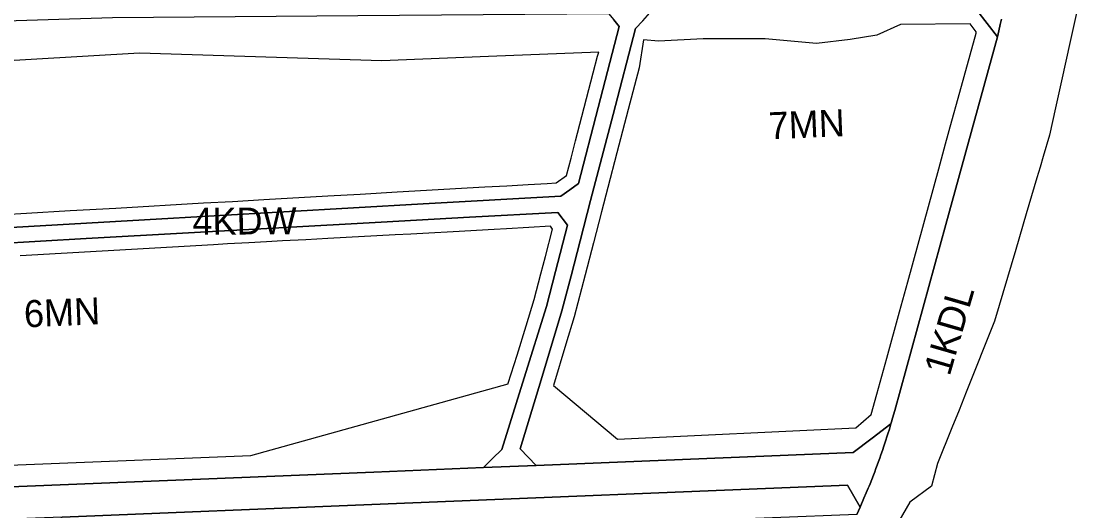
# Model space of a CAD drawing. Extents: x 7418021 to 7419743, y 5540231 to 5541685.
# Drawn here: x 7419339.9 to 7419732.3, y 5540844.3 to 5541025.9 of the extents above; entities that cross this region are included whole.
import ezdxf

# ---------------------------------------------------------------- set-up
doc = ezdxf.new("R2010")
doc.units = 0
for name, color, linetype in [('linie_rozgraniczajace', 7, 'Continuous'), ('linie_zabudowy_nieprzekraczalne', 7, 'Continuous'), ('linie_zabudowy_obowiazujace', 7, 'Continuous'), ('oznaczenia_przeznaczen', 7, 'Continuous')]:
    doc.layers.add(name, color=color, linetype=linetype)

msp = doc.modelspace()

# ---------------------------------------------------------------- linework, layer by layer
at = {"layer": 'linie_rozgraniczajace'}
for points in [[(7419573.14, 5541028.94), (7419627.51, 5541029.4), (7419694.39, 5541029.96), (7419702.04, 5541020.06), (7419682.92, 5540950.48), (7419663.99, 5540881.59), (7419663.17, 5540878.7), (7419662.77, 5540877.34), (7419662.54, 5540876.55), (7419655.53, 5540871.26), (7419648.52, 5540865.96), (7419530.9, 5540861.18), (7419527.93, 5540864.25), (7419524.97, 5540867.31), (7419532.73, 5540892.9), (7419540.49, 5540918.5), (7419543.88, 5540931.49), (7419547.26, 5540944.48), (7419551.14, 5540959.4), (7419559.45, 5540991.31), (7419567.76, 5541023.22), (7419570.45, 5541026.08)], [(7419095.29, 5541018.74), (7419234.54, 5541023), (7419373.79, 5541027.27), (7419464.79, 5541028.03), (7419557.71, 5541028.81), (7419559.74, 5541026.38), (7419561.78, 5541023.94), (7419553.94, 5540993.88), (7419546.61, 5540965.74), (7419543.38, 5540963.37), (7419540.14, 5540961), (7419488.96, 5540958.13), (7419385.59, 5540952.23), (7419282.22, 5540946.32), (7419257.39, 5540947.92), (7419232.55, 5540949.52), (7419183.71, 5540952.61), (7419134.88, 5540955.7), (7419086.04, 5540958.8), (7419083.17, 5540961.6), (7419080.29, 5540964.41), (7419084.37, 5541008.48)], [(7419355.09, 5540842.04), (7419469.94, 5540846.7), (7419646.42, 5540853.87), (7419651.11, 5540845.7), (7419649.87, 5540842.99), (7419587.34, 5540840.46), (7419524.8, 5540837.92), (7419498.8, 5540836.95), (7419498.21, 5540816.69), (7419497.63, 5540796.42), (7419468.2, 5540795.38), (7419438.78, 5540794.34), (7419439.03, 5540813.98), (7419439.29, 5540833.62), (7419394.19, 5540831.79), (7419349.1, 5540829.96), (7419349.21, 5540833.97), (7419352.15, 5540838.02)]]:
    msp.add_lwpolyline(points, close=True, dxfattribs=at)
for points in [[(7419732.26, 5541032.84), (7419729.06, 5541018.33), (7419725.85, 5541003.82), (7419723.64, 5540993.74), (7419721.43, 5540983.66), (7419719.06, 5540975.72), (7419717.88, 5540971.76), (7419716.7, 5540967.79), (7419712.77, 5540954.52), (7419708.85, 5540941.26), (7419701.01, 5540914.73), (7419690.44, 5540888.3), (7419687.8, 5540881.69), (7419685.16, 5540875.09), (7419679.88, 5540861.87), (7419677.58, 5540853.52), (7419669.56, 5540847.51), (7419663.65, 5540837.34)], [(7419703.59, 5541026.71), (7419703.12, 5541024.71), (7419702.58, 5541022.37), (7419702.04, 5541020.06), (7419694.39, 5541029.96)], [(7419282.22, 5540946.32), (7419385.59, 5540952.23), (7419488.96, 5540958.13), (7419540.14, 5540961), (7419543.38, 5540963.37), (7419546.61, 5540965.74), (7419553.94, 5540993.88), (7419561.78, 5541023.94), (7419559.74, 5541026.38)], [(7419570.45, 5541026.08), (7419567.76, 5541023.22), (7419559.45, 5540991.31), (7419551.14, 5540959.4), (7419547.26, 5540944.48), (7419543.88, 5540931.49), (7419540.49, 5540918.5), (7419532.73, 5540892.9), (7419524.97, 5540867.31), (7419527.93, 5540864.25), (7419530.9, 5540861.18), (7419511.34, 5540860.39), (7419514.75, 5540863.76), (7419518.16, 5540867.14), (7419526.45, 5540893.63), (7419534.73, 5540920.11), (7419538.1, 5540933.05), (7419542.61, 5540950.29), (7419538.92, 5540955), (7419506.15, 5540953.18), (7419473.38, 5540951.36), (7419363.96, 5540945.38), (7419313.1, 5540942.32)], [(7419663.17, 5540878.7), (7419663.99, 5540881.59), (7419682.92, 5540950.48), (7419702.04, 5541020.06), (7419702.58, 5541022.37), (7419703.12, 5541024.71), (7419703.59, 5541026.71)], [(7419313.1, 5540942.32), (7419363.96, 5540945.38), (7419473.38, 5540951.36), (7419506.15, 5540953.18), (7419538.92, 5540955), (7419542.61, 5540950.29), (7419538.1, 5540933.05), (7419534.73, 5540920.11), (7419526.45, 5540893.63), (7419518.16, 5540867.14), (7419514.75, 5540863.76), (7419511.34, 5540860.39), (7419470.75, 5540858.74), (7419292.97, 5540851.53)], [(7419292.97, 5540851.53), (7419470.75, 5540858.74), (7419511.34, 5540860.39), (7419530.9, 5540861.18), (7419648.52, 5540865.96), (7419655.53, 5540871.26), (7419662.54, 5540876.55), (7419662.25, 5540875.58), (7419661.96, 5540874.62), (7419661.42, 5540872.89), (7419661.05, 5540871.73), (7419660.68, 5540870.57), (7419660.31, 5540869.44), (7419659.94, 5540868.31), (7419659.38, 5540866.68), (7419658.82, 5540865.05), (7419658.39, 5540863.86), (7419657.96, 5540862.66), (7419657.48, 5540861.34), (7419656.99, 5540860.02), (7419656.52, 5540858.8), (7419656.06, 5540857.57), (7419655.43, 5540855.99), (7419654.81, 5540854.4), (7419654.46, 5540853.55), (7419654.11, 5540852.7), (7419653.76, 5540851.86), (7419653.41, 5540851.02), (7419652.55, 5540848.99), (7419651.11, 5540845.7), (7419646.42, 5540853.87)], [(7419649.87, 5540842.99), (7419651.11, 5540845.7), (7419652.55, 5540848.99), (7419653.41, 5540851.02), (7419653.76, 5540851.86), (7419654.11, 5540852.7), (7419654.46, 5540853.55), (7419654.81, 5540854.4), (7419655.43, 5540855.99), (7419656.06, 5540857.57), (7419656.52, 5540858.8), (7419656.99, 5540860.02), (7419657.48, 5540861.34), (7419657.96, 5540862.66), (7419658.39, 5540863.86), (7419658.82, 5540865.05), (7419659.38, 5540866.68), (7419659.94, 5540868.31), (7419660.31, 5540869.44), (7419660.68, 5540870.57), (7419661.05, 5540871.73), (7419661.42, 5540872.89), (7419661.96, 5540874.62), (7419662.25, 5540875.58), (7419662.54, 5540876.55), (7419662.77, 5540877.34), (7419663.17, 5540878.7)], [(7419646.42, 5540853.87), (7419469.94, 5540846.7), (7419355.09, 5540842.04), (7419331.92, 5540841.1)]]:
    msp.add_lwpolyline(points, dxfattribs=at)
at = {"layer": 'linie_zabudowy_nieprzekraczalne'}
for points in [[(7419666.05, 5541024.72), (7419657.27, 5541020.78)], [(7419691.95, 5541024.94), (7419666.05, 5541024.72)], [(7419694.22, 5541021.98), (7419691.95, 5541024.94)], [(7419694.14, 5541021.48), (7419694.22, 5541021.98)], [(7419570.75, 5541019), (7419569.11, 5541008.55)], [(7419576.36, 5541018.55), (7419570.75, 5541019)], [(7419592.84, 5541019.34), (7419576.36, 5541018.55)], [(7419603.97, 5541019.4), (7419592.84, 5541019.34)], [(7419615.85, 5541019.32), (7419603.97, 5541019.4)], [(7419634.88, 5541017.6), (7419615.85, 5541019.32)], [(7419647.37, 5541019.09), (7419634.88, 5541017.6)], [(7419657.27, 5541020.78), (7419647.37, 5541019.09)], [(7419687.52, 5540997.38), (7419694.14, 5541021.48)], [(7419383.77, 5541014.03), (7419244.03, 5541005.91)], [(7419473.67, 5541011.16), (7419383.77, 5541014.03)], [(7419554.13, 5541014.43), (7419513.21, 5541012.77)], [(7419553.73, 5541012.87), (7419554.13, 5541014.43)], [(7419513.21, 5541012.77), (7419473.67, 5541011.16)], [(7419552.13, 5541006.75), (7419553.73, 5541012.87)], [(7419546.32, 5540984.44), (7419552.13, 5541006.75)], [(7419569.11, 5541008.55), (7419565.11, 5540993.19)], [(7419685.2, 5540988.94), (7419687.52, 5540997.38)], [(7419565.11, 5540993.19), (7419560.92, 5540977.13)], [(7419682.85, 5540980.42), (7419685.2, 5540988.94)], [(7419545.58, 5540981.59), (7419546.32, 5540984.44)], [(7419544.55, 5540977.64), (7419545.06, 5540979.59)], [(7419545.06, 5540979.59), (7419545.58, 5540981.59)], [(7419680.32, 5540971.2), (7419682.85, 5540980.42)], [(7419542.22, 5540968.73), (7419543.88, 5540975.08)], [(7419543.88, 5540975.08), (7419544.55, 5540977.64)], [(7419560.92, 5540977.13), (7419557.56, 5540964.2)], [(7419668.78, 5540929.2), (7419680.32, 5540971.2)], [(7419538.39, 5540965.91), (7419542.22, 5540968.73)], [(7419479.41, 5540962.6), (7419511.95, 5540964.43)], [(7419511.95, 5540964.43), (7419520.07, 5540964.89)], [(7419520.07, 5540964.89), (7419527.92, 5540965.33)], [(7419527.92, 5540965.33), (7419534.99, 5540965.72)], [(7419534.99, 5540965.72), (7419538.39, 5540965.91)], [(7419557.56, 5540964.2), (7419555.22, 5540955.23)], [(7419407.52, 5540958.49), (7419418.25, 5540959.1)], [(7419418.25, 5540959.1), (7419429.94, 5540959.77)], [(7419429.94, 5540959.77), (7419453.61, 5540961.12)], [(7419453.61, 5540961.12), (7419465.63, 5540961.81)], [(7419465.63, 5540961.81), (7419479.41, 5540962.6)], [(7419341.84, 5540954.74), (7419358.07, 5540955.66)], [(7419358.07, 5540955.66), (7419374.99, 5540956.63)], [(7419374.99, 5540956.63), (7419407.52, 5540958.49)], [(7419555.22, 5540955.23), (7419552.22, 5540943.69)], [(7419325.1, 5540953.78), (7419341.84, 5540954.74)], [(7419491.14, 5540947.34), (7419484.42, 5540946.97)], [(7419500.11, 5540947.84), (7419491.14, 5540947.34)], [(7419515.39, 5540948.69), (7419500.11, 5540947.84)], [(7419519.97, 5540948.94), (7419515.39, 5540948.69)], [(7419528.26, 5540949.4), (7419519.97, 5540948.94)], [(7419536.29, 5540949.85), (7419528.26, 5540949.4)], [(7419534.39, 5540938.66), (7419537.03, 5540948.76)], [(7419537.03, 5540948.76), (7419536.29, 5540949.85)], [(7419416.45, 5540943.31), (7419411.21, 5540943.03)], [(7419424.3, 5540943.73), (7419416.45, 5540943.31)], [(7419430.93, 5540944.09), (7419424.3, 5540943.73)], [(7419436.87, 5540944.4), (7419430.93, 5540944.09)], [(7419445.51, 5540944.87), (7419436.87, 5540944.4)], [(7419453.62, 5540945.3), (7419445.51, 5540944.87)], [(7419478.66, 5540946.65), (7419453.62, 5540945.3)], [(7419484.42, 5540946.97), (7419478.66, 5540946.65)], [(7419552.22, 5540943.69), (7419549.13, 5540931.83)], [(7419411.21, 5540943.03), (7419339.5, 5540938.9)], [(7419532.71, 5540932.19), (7419534.39, 5540938.66)], [(7419530.25, 5540922.72), (7419532.71, 5540932.19)], [(7419549.13, 5540931.83), (7419545.04, 5540916.26)], [(7419665.73, 5540918.13), (7419668.78, 5540929.2)], [(7419527.26, 5540912.97), (7419530.25, 5540922.72)], [(7419545.04, 5540916.26), (7419541.99, 5540906.18)], [(7419661.02, 5540900.97), (7419665.73, 5540918.13)], [(7419523.86, 5540902.11), (7419527.26, 5540912.97)], [(7419541.99, 5540906.18), (7419537.31, 5540890.78)], [(7419520.59, 5540891.64), (7419523.86, 5540902.11)], [(7419657.34, 5540887.59), (7419661.02, 5540900.97)], [(7419520.53, 5540891.44), (7419520.59, 5540891.64)], [(7419655.23, 5540880.04), (7419657.34, 5540887.59)], [(7419649.55, 5540875.12), (7419655.23, 5540880.04)]]:
    msp.add_lwpolyline(points, dxfattribs=at)
at = {"layer": 'linie_zabudowy_obowiazujace'}
for points in [[(7419425.02, 5540864.9), (7419520.53, 5540891.44)], [(7419537.31, 5540890.78), (7419561.11, 5540870.87)], [(7419186.8, 5540873.19), (7419240.33, 5540863.27), (7419266.86, 5540859.9), (7419292.65, 5540859.52), (7419344.76, 5540861.64)], [(7419561.11, 5540870.87), (7419649.55, 5540875.12)], [(7419344.76, 5540861.64), (7419425.02, 5540864.9)]]:
    msp.add_lwpolyline(points, dxfattribs=at)

# ---------------------------------------------------------------- texts
at = {"layer": 'oznaczenia_przeznaczen'}
for s, rotation, p in [('7MN', 2.396, (7419617.38, 5540982.09)), ('4KDW', 0.3694, (7419403.45, 5540946.68)), ('1KDL', 73.8697, (7419684.31, 5540894)), ('6MN', 2.396, (7419341.12, 5540912.35))]:
    msp.add_text(s, height=10, rotation=rotation, dxfattribs=at).set_placement(p)

doc.saveas('drawing.dxf')
